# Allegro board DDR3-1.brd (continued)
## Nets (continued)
DRAM_BA2: U1.AB12 U2.M3 U3.M3 U4.M3 U5.M3
DRAM_CAS#: U1.AE16 U2.K3 U3.K3 U4.K3 U5.K3
DRAM_CK0: R19.2 U1.AD15 U4.J7 U5.J7
DRAM_CK0#: R19.1 U1.AE15 U4.K7 U5.K7
DRAM_CK1: R18.2 U1.AD14 U2.J7 U3.J7
DRAM_CK1#: R18.1 U1.AE14 U2.K7 U3.K7
DRAM_CKE0: R224.1 U1.Y11 U2.K9 U3.K9 U4.K9 U5.K9
DRAM_CKE1: U1.AA11
DRAM_CS0#: U1.Y16 U2.L2 U3.L2 U4.L2 U5.L2
DRAM_CS1#: U1.AD17
DRAM_D00: U1.AD2 U2.E3
DRAM_D01: U1.AE2 U2.H7
DRAM_D02: U1.AC4 U2.F8
DRAM_D03: U1.AA5 U2.H8
DRAM_D04: U1.AC1 U2.G2
DRAM_D05: U1.AD1 U2.F2
DRAM_D06: U1.AB4 U2.H3
DRAM_D07: U1.AE4 U2.F7
DRAM_D08: U1.AD5 U2.D7
DRAM_D09: U1.AE5 U2.C8
DRAM_D10: U1.AA6 U2.A3
DRAM_D11: U1.AE7 U2.B8
DRAM_D12: U1.AB5 U2.A2
DRAM_D13: U1.AC5 U2.C2
DRAM_D14: U1.AB6 U2.C3
DRAM_D15: U1.AC7 U2.A7
DRAM_D16: U1.AB7 U3.E3
DRAM_D17: U1.AA8 U3.H3
DRAM_D18: U1.AB9 U3.H8
DRAM_D19: U1.Y9 U3.F8
DRAM_D20: U1.Y7 U3.G2
DRAM_D21: U1.Y8 U3.F2
DRAM_D22: U1.AC8 U3.H7
DRAM_D23: U1.AA9 U3.F7
DRAM_D24: U1.AE9 U3.D7
DRAM_D25: U1.Y10 U3.A2
DRAM_D26: U1.AE11 U3.B8
DRAM_D27: U1.AB11 U3.A3
DRAM_D28: U1.AC9 U3.C2
DRAM_D29: U1.AD9 U3.C3
DRAM_D30: U1.AD11 U3.A7
DRAM_D31: U1.AC11 U3.C8
DRAM_D32: U1.AA17 U4.E3
DRAM_D33: U1.AA18 U4.F7
DRAM_D34: U1.AC18 U4.F2
DRAM_D35: U1.AE19 U4.F8
DRAM_D36: U1.Y17 U4.H3
DRAM_D37: U1.Y18 U4.H8
DRAM_D38: U1.AB19 U4.G2
DRAM_D39: U1.AC19 U4.H7
DRAM_D40: U1.Y19 U4.D7
DRAM_D41: U1.AB20 U4.C3
DRAM_D42: U1.AB21 U4.C8
DRAM_D43: U1.AD21 U4.C2
DRAM_D44: U1.Y20 U4.A7
DRAM_D45: U1.AA20 U4.A2
DRAM_D46: U1.AE21 U4.B8
DRAM_D47: U1.AC21 U4.A3
DRAM_D48: U1.AC22 U5.E3
DRAM_D49: U1.AE22 U5.F7
DRAM_D50: U1.AE24 U5.F2
DRAM_D51: U1.AC24 U5.F8
DRAM_D52: U1.AB22 U5.H3
DRAM_D53: U1.AC23 U5.H8
DRAM_D54: U1.AD25 U5.G2
DRAM_D55: U1.AC25 U5.H7
DRAM_D56: U1.AB25 U5.D7
DRAM_D57: U1.AA21 U5.C3
DRAM_D58: U1.Y25 U5.C8
DRAM_D59: U1.Y22 U5.C2
DRAM_D60: U1.AB23 U5.A7
DRAM_D61: U1.AA23 U5.A2
DRAM_D62: U1.Y23 U5.B8
DRAM_D63: U1.W25 U5.A3
DRAM_DQM0: U1.AC3 U2.E7
DRAM_DQM1: U1.AC6 U2.D3
DRAM_DQM2: U1.AB8 U3.E7
DRAM_DQM3: U1.AE10 U3.D3
DRAM_DQM4: U1.AB18 U4.E7
DRAM_DQM5: U1.AC20 U4.D3
DRAM_DQM6: U1.AD24 U5.E7
DRAM_DQM7: U1.Y21 U5.D3
DRAM_DQS0: U1.AE3 U2.F3
DRAM_DQS0#: U1.AD3 U2.G3
DRAM_DQS1: U1.AD6 U2.C7
DRAM_DQS1#: U1.AE6 U2.B7
DRAM_DQS2: U1.AD8 U3.F3
DRAM_DQS2#: U1.AE8 U3.G3
DRAM_DQS3: U1.AC10 U3.C7
DRAM_DQS3#: U1.AB10 U3.B7
DRAM_DQS4: U1.AD18 U4.F3
DRAM_DQS4#: U1.AE18 U4.G3
DRAM_DQS5: U1.AD20 U4.C7
DRAM_DQS5#: U1.AE20 U4.B7
DRAM_DQS6: U1.AD23 U5.F3
DRAM_DQS6#: U1.AE23 U5.G3
DRAM_DQS7: U1.AA25 U5.C7
DRAM_DQS7#: U1.AA24 U5.B7
DRAM_ODT0: U1.AC16 U2.K1 U3.K1 U4.K1 U5.K1
DRAM_ODT1: U1.AB17
DRAM_RAS#: U1.AB15 U2.J3 U3.J3 U4.J3 U5.J3
DRAM_RST#: R13.1 U1.Y6 U2.T2 U3.T2 U4.T2 U5.T2
DRAM_WE#: U1.AB16 U2.L3 U3.L3 U4.L3 U5.L3
DSI_CLK0M: U1.H3
DSI_CLK0P: U1.H4
DSI_D0M: U1.G2
DSI_D0P: U1.G1
DSI_D1M: U1.H2
DSI_D1P: U1.H1
EIM_A16: U1.H25
EIM_A17: U1.G24
EIM_A18: R125.2 U1.J22
EIM_A19: U1.G25
EIM_A20: R127.2 U1.H22
EIM_A21: R128.2 U1.H23
EIM_A22: U1.F24
EIM_A23: R130.2 U1.J21
EIM_A24: U1.F25
EIM_DA0: R107.2 U1.L20
EIM_DA1: R108.2 U1.J25
EIM_DA2: R109.2 U1.L21
EIM_DA3: R110.2 U1.K24
EIM_DA4: R138.2 U1.L22
EIM_DA5: R139.2 U1.L23
EIM_DA6: R140.2 U1.K25
EIM_DA7: R141.2 U1.L25
EIM_DA8: U1.L24
EIM_DA9: R142.2 U1.M21
EIM_DA10: U1.M22
EIM_DA11: R144.2 U1.M20
EIM_DA12: R145.2 U1.M24
EIM_DA13: R146.2 U1.M23
EIM_DA14: R147.2 U1.N23
EIM_DA15: U1.N24
EIM_EB0: R148.2 U1.K21
EIM_EB1: R134.2 U1.K23
EIM_EB2: R136.2 U1.E22
EIM_EB3: R137.2 U1.F23
EIM_LBA: R133.2 U1.K22
EIM_RW: U1.K20
EIM_WAIT: U1.M25
EXP2_27: J6.27 R171.2
EXP2_28: J6.28 R181.1
EXP2_29: J6.29 R172.2
EXP2_30: J6.30 R182.1
EXP2_31: J6.31 R173.2
EXP2_32: J6.32 R183.1
EXP2_33: J6.33 R174.2
EXP2_34: J6.34 R184.1
EXP2_35: J6.35 R175.2
EXP2_36: J6.36 R185.1
FEC_CRS_DV: U1.U21
FEC_LED1: J5.51
FEC_LED2: J5.52
FEC_MDC: U1.V20
FEC_MDIO: R70.1 U1.V23
FEC_PWR: C152.2 J5.79 J7.36 R82.1
FEC_RST#: R71.1
FEC_RX+: J5.77 R190.1
FEC_RX-: J5.78 R191.1
FEC_RXD0: U1.W21
FEC_RXD1: U1.W22
FEC_RXER: U1.W23
FEC_TX+: J5.75 R188.1
FEC_TX-: J5.76 R189.1
FEC_TXD0: U1.U20
FEC_TXD1: U1.W20
FEC_TXEN: U1.V21
GP1_02: U1.T1
GP1_04: U1.R6
GP3_19: U1.G21
GP3_28: U1.G23
GP3_29: U1.J19
GP4_14: U1.T6
GP4_15: U1.V5
GP7_05: U1.P5
GP7_13: U1.P6
GPIO_16: U1.R2
HDMI_CLKM: J6.39 U1.J5
HDMI_CLKP: J6.40 U1.J6
HDMI_D0M: J6.41 U1.K5
HDMI_D0P: J6.42 U1.K6
HDMI_D1M: J6.43 U1.J3
HDMI_D1P: J6.44 U1.J4
HDMI_D2M: J6.45 U1.K3
HDMI_D2P: J6.46 U1.K4
HDMI_DDCCEC: J6.48 U1.K2
HDMI_HPD: J6.47 U1.K1
HDMI_VP: C122.2 U1.L7
HDMI_VPH: C124.2 U1.M7
HP_L: J5.69 J7.39 U15.30
HP_R: J5.70 J7.40 U15.29
I2C1_SCL: J6.62 Q4.2 R63.2 U1.N5 U15.16
I2C1_SDA: J6.61 Q3.2 R62.2 U1.N6 U15.17
I2C2_SCL: J5.72 R97.2 U1.U5
I2C2_SDA: J5.71 R96.2 U1.T7
I2C3_SCL: R99.2 U1.R4
I2C3_SDA: R98.2 U1.T3
I2S_MCLK: J5.44 R164.2 R223.2 U15.11
IOB: C178.2 L1.1 R155.2
IOG: C181.2 L3.1 R156.2
IOR: C184.2 L5.1 R157.2
JTAG_MOD: J7.12 U1.H6
JTAG_RST#: D11.1 J7.13
JTAG_TCK: J7.10 U1.H5
JTAG_TDI: J7.8 U1.G5
JTAG_TDO: J7.11 U1.G6
JTAG_TMS: J7.9 U1.C3
JTAG_TRSTB: J7.7 U1.C2
LVDS0_CLK_N: J6.71 U1.V4
LVDS0_CLK_P: J6.72 U1.V3
LVDS0_TX0_N: J6.65 U1.U2
LVDS0_TX0_P: J6.66 U1.U1
LVDS0_TX1_N: J6.67 U1.U4
LVDS0_TX1_P: J6.68 U1.U3
LVDS0_TX2_N: J6.69 U1.V2
LVDS0_TX2_P: J6.70 U1.V1
LVDS0_TX3_N: J6.73 U1.W2
LVDS0_TX3_P: J6.74 U1.W1
LVDS1_CLK_N: R174.1 U1.Y3
LVDS1_CLK_P: R184.2 U1.Y4
LVDS1_TX0_N: R171.1 U1.Y1
LVDS1_TX0_P: R181.2 U1.Y2
LVDS1_TX1_N: R172.1 U1.AA2
LVDS1_TX1_P: R182.2 U1.AA1
LVDS1_TX2_N: R173.1 U1.AB1
LVDS1_TX2_P: R183.2 U1.AB2
LVDS1_TX3_N: R175.1 U1.AA3
LVDS1_TX3_P: R185.2 U1.AA4
LVDS_2V5: C128.2 C129.2 R61.2 U1.V7
MIC: C199.1 J5.68 J7.38 R165.1
NANDF_ALE: U1.A16
NANDF_CLE: U1.C15
NANDF_CS0: R34.1 U1.F15
NANDF_CS1: R35.1 U1.C16
NANDF_CS2: R36.1 U1.A17
NANDF_CS3: R37.1 U1.D16
NANDF_D0: U1.A18
NANDF_D1: U1.C17
NANDF_D2: U1.F16
NANDF_D3: U1.D17
NANDF_D4: U1.A19
NANDF_D5: U1.B18
NANDF_D6: U1.E17
NANDF_D7: U1.C18
NANDF_RB0: R38.1 U1.B16
NANDF_RE#: R32.1
NANDF_WE#: R31.1
NANDF_WP#: R39.1 U1.E15
NVCC_CSI: C127.2 R60.2 R62.1 R63.1 R159.1 R161.1 U1.N7
NVCC_LCD: C126.2 U1.P19
ON_KEY_DET: Q9.3 R194.2 U1.R5
PCIE_CLK_N: J6.23 U1.C7
PCIE_CLK_P: J6.24 U1.D7
PCIE_RXM: J6.19 U1.B1
PCIE_RXP: J6.20 U1.B2
PCIE_TXM: J6.21 U1.A3
PCIE_TXP: J6.22 U1.B3
PCIE_VP: C133.2 C134.2 R67.2 U1.H7
PCIE_VPH: C137.2 C138.2 R68.2 U1.G7
PCIE_VPTX: C135.2 C136.2 FB1.2 U1.G8
PLL_1V1: U1.E8
PWM2: J6.75 U1.T4
PWR_ON_REQ: R197.2 U1.D11
RGMII_RD0: U1.C24
RGMII_RD1: U1.B23
RGMII_RD2: U1.B24
RGMII_RD3: U1.D23
RGMII_RX_CTL: U1.D22
RGMII_RXC: U1.B25
RGMII_TD0: U1.C22
RGMII_TD2: U1.E21
RGMII_TD3: U1.A24
RGMII_TX1: U1.F20
RGMII_TX_CTL: U1.C23
RGMII_TXC: U1.D21
SATA_RXM: J6.2 U1.A14
SATA_RXP: J6.1 U1.B14
SATA_TXM: J6.3 U1.B12
SATA_TXP: J6.4 U1.A12
SATA_VP: C155.2 C156.2 R83.2 U1.G13
SATA_VPH: C157.2 C158.2 R84.2 U1.G12
SD1_CD#: J5.21 R41.1 U1.H19
SD1_CLK: J5.16 R20.2
SD1_CMD: J5.15 U1.B21
SD1_DATA0: J5.17 U1.A21
SD1_DATA1: J5.18 U1.C20
SD1_DATA2: J5.19 U1.E19
SD1_DATA3: J5.20 U1.F18
SD1_WP: J5.22 R40.1 U1.N22
SD3_CD#: J5.35 R44.1 U1.D15
SD3_CLK: J5.26
SD3_CMD: J5.25 U1.B13
SD3_DATA0: J5.27 U1.E14
SD3_DATA1: J5.28 U1.F14
SD3_DATA2: J5.29 U1.A15
SD3_DATA3: J5.30 U1.B15
SD3_DATA4: J5.31 U1.D13
SD3_DATA5: J5.32 U1.C13
SD3_DATA6: J5.33 U1.E13
SD3_DATA7: J5.34 U1.F13
SD3_WP: J5.36 R45.1 U1.G20
SD4_CLK: R22.2 R31.2
SD4_CMD: R30.1 R32.2 U1.B17
SD4_DATA0: U1.D18
SD4_DATA1: U1.B19
SD4_DATA2: U1.F17
SD4_DATA3: U1.A20
SD4_DATA4: U1.E18
SD4_DATA5: U1.C19
SD4_DATA6: U1.B20
SD4_DATA7: U1.D19
SPDIF_OUT1: J6.76 U1.R1
SYS_POR#: J5.50 Q1.1 R200.2 U1.C11
SYS_PWR_ON: Q8.1 R196.2 U1.R3
SYS_WDOG#: D12.1 U1.T2
TAMPER: J2.2 U1.E11
UART1_RXD: J5.74 J7.17 U1.M3
UART1_TXD: J5.73 J7.16 U1.M1
UART2_RXD: J5.54 U1.E25
UART2_TXD: J5.53 U1.E24
UART3_CTS: U1.D25
UART3_RXD: J5.56 U1.G22
UART3_TXD: J5.55 U1.F22
UART4_RXD: U1.V6
UART4_TXD: U1.W5
UART5_RXD: U1.U6
UART5_TXD: U1.U7
USB5V: J6.13 R85.2
USB5V_OTG: C159.2 J6.7 J7.1 R87.2
USB5V_PWR: J6.18 U1.H21
USB_H1_DN: J6.14 U1.F10
USB_H1_DP: J6.15 U1.E10
USB_HUB_RST#: J6.17 U1.J20
USBH1_VBUS: R85.1 U1.D10
USBOTG_CHD#: U1.B8
USBOTG_DN: J6.8 R186.1 U1.B6
USBOTG_DP: J6.9 R187.1 U1.A6
USBOTG_OC: J6.11 U1.H20
USBOTG_PWR: J6.12 U1.E23
USBOTG_VBUS: C161.2 U1.E9
VGA_BLUE: C180.2 J5.57 J7.28 L2.2
VGA_GREEN: C183.2 J5.58 J7.26 L4.2
VGA_HSYNC: D8.3 J5.61 J7.22
VGA_RED: C186.2 J5.59 J7.24 L6.2
VGA_VSYNC: D9.3 J5.62 J7.21
VSNVS_3V0: C163.2 D3.3 R92.2 R149.2 R150.2 R151.2 U1.G11
VSNVS_CAP: C164.2 C165.2 U1.G9

Pads without a net: FM1 1; FM2 1; FM3 1; FM4 1; FM* 1; FM*#2 1; FM*#3 1; FM*#4 1; U1 A9 A10 A11 B9 B10 B11 C8; U2 J1 J9 L1 L9; U3 J1 J9 L1 L9; U4 J1 J9 L1 L9; U5 J1 J9 L1 L9; U15 3 4 5 6 15 19 20 36; U16 1

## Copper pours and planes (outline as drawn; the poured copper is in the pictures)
1V1 on POWER05 (solid shape): 27.83,50.44 27.83,48.49 27.34,48 26.45,48 23.02,44.57 18.96,44.57 15,40.61 15,36.85 15.4,36.44 14.87,35.92 14.87,32.78 15.66,32 21.63,32 26.96,26.67 59.09,26.67 59.32,26.43 59.32,17.12 58.71,16.51 56,16.51 52.19,20.32 26.92,20.32 24.12,23.11 19.68,23.11 11.32,31.47 11.32,43.32 17.52,49.53 24.5,49.53 25.65,50.67 27.6,50.67
3V3 on POWER05 (solid shape): 72.91,43.92 72.58,43.58 69.79,43.58 68.98,44.4 68.98,52.55 67.68,53.84 64.89,53.84 62.22,56.51 48.38,56.51 48.02,56.87 48.02,65.25 47.24,66.04 37.12,66.04 36.21,65.13 36.21,60.72 37.37,59.56 40.8,59.56 41.16,59.2 41.16,58.03 41.27,43.18 31.66,43.18 30.49,42.01 30.49,39.01 35.58,33.92 35.19,33.53 35.19,31.85 34.71,31.36 31.62,31.36 26.28,36.7 15.87,36.7 15.51,37.06 15.51,40.4 19.17,44.06 23.23,44.06 26.66,47.49 27.55,47.49 28.34,48.28 28.34,50.65 27.81,51.18 25.44,51.18 24.29,50.03 17.31,50.03 10.81,43.54 10.81,31.26 19.47,22.6 23.91,22.6 26.71,19.81 51.98,19.81 55.79,16 58.56,16 58.56,14.37 59.98,12.95 61.59,12.95 62.5,13.86 62.5,23.74 66.71,23.74 67.07,23.39 67.07,14.88 68.62,13.33 70.75,13.33 70.75,10.01 69.76,9.01 14.51,9.01 13.35,7.85 13.35,1.02 1.02,1.02 1.02,73.98 72.91,73.98
GND on GND02 (solid shape): 99.49,10 99.49,0.51 0.51,0.51 0.51,74.49 99.49,74.49
GND on GND07 (solid shape): 99.49,10 99.49,0.51 0.51,0.51 0.51,74.49 99.49,74.49
VCC_DDR on POWER05 (solid shape): 98.98,8.5 98.98,1.02 13.86,1.02 13.86,7.64 14.73,8.5 69.97,8.5 71.26,9.8 71.26,23.72 69.99,24.99 69.99,26.77 69.61,27.15 69.61,32.87 67.71,34.8 67.71,37.99 69.11,39.39 69.13,39.39 69.28,39.54 69.28,42.51 69.84,43.07 72.79,43.07 73.42,43.71 73.42,73.98 98.98,73.98
VCC_EIM on POWER05 (solid shape): 47.51,65.04 47.51,56.66 48.17,56 62.01,56 64.68,53.34 67.47,53.34 68.47,52.34 68.47,44.19 69.35,43.3 68.77,42.72 68.77,39.78 67.45,38.46 67,38.91 43.22,38.93 41.8,40.36 41.78,42.8 41.8,42.82 41.8,43.03 41.78,43.05 41.67,58.04 41.67,59.41 41.01,60.07 37.59,60.07 36.72,60.93 36.72,64.91 37.33,65.53 47.03,65.53
VDDARM23 on POWER05 (solid shape): 69.1,32.66 69.1,31.87 35.7,31.87 35.7,33.32 36.04,33.65 66.72,33.63 67.44,34.34
VDDARM23_IN on POWER05 (solid shape): 31.41,30.86 34.92,30.86 35.43,31.36 69.1,31.36 69.1,29.71 59.85,29.71 59.45,29.31 59.45,27.53 59.09,27.17 27.17,27.17 21.84,32.51 15.87,32.51 15.38,32.99 15.38,35.7 15.87,36.19 26.07,36.19
VDDARM_IN on POWER05 (solid shape): 41.29,40.15 43.01,38.43 66.79,38.4 67.2,37.99 67.2,34.82 66.51,34.13 36.06,34.16 31,39.22 31,41.8 31.87,42.67 41.27,42.67
HDMI_VP on POWER05 (solid shape): 61.99,14.07 61.38,13.46 60.19,13.46 59.07,14.58 59.07,16.15 59.83,16.91 59.83,26.64 59.56,26.92 59.96,27.32 59.96,29.1 60.06,29.21 61.99,29.21
HDMI_VPH on POWER05 (solid shape): 69.1,26.94 69.48,26.56 69.48,24.78 70.75,23.51 70.75,13.84 68.83,13.84 67.58,15.09 67.58,23.6 66.92,24.25 62.5,24.25 62.5,29.21 69.1,29.21

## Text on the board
Ref Des/Silkscreen Bottom: B | A
Ref Des/Silkscreen Top: B | A
User.5: FIGURE | SIZE | 8.0 | 28.0 | 40.0 | 87.0 | DRILL CHART: TOP to BOTTOM | ALL UNITS ARE IN MILS | PLATED | NON-PLATED | QTY | 1793 | 160 | 29 | 4
